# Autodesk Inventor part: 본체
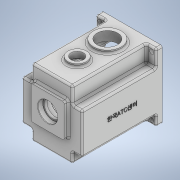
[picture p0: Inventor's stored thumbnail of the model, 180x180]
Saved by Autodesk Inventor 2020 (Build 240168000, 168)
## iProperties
Created: 2022-01
Part Number: 본체
Material: 일반
Document SubType Name: Modeling
Designer: user
Density: 1 g/cm^3
Appearance: 기본값
Author: user
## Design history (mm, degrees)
sketch "스케치1"
  geometry: L1 (-49, 55)-(49, 55); L2 (49, 55)-(49, -55); L3 (49, -55)-(-49, -55); L4 (-49, -55)-(-49, 55); L5 (-49, 55)-(49, -55); L6 (49, 55)-(-49, -55); 1 further point
  constraints: 12 end point, 2 midpoint, 2 parallel, 1 horizontal, 1 perpendicular
  dimensions: "d0" = 98 distance of L2.end L3.end; "d1" = 110 distance of L1.end L2.end
extrude "돌출1" new body sketch "스케치1" distance "d2" = 10; taper "d3" = 0 deg
sketch "스케치2"
  geometry: L1 (49, 55)-(-49, 55) reference; L2 (-49, 55)-(-33, 55); L3 (-33, 55)-(-33, 28); L4 (-33, 28)-(-49, 28); L5 (-49, 28)-(-49, 55); L6 (49, -55)-(49, 55) reference; L7 (49, 55)-(33, 55); L8 (33, 55)-(33, 28); L9 (33, 28)-(49, 28); L10 (49, 28)-(49, 55); L11 (-49, -55)-(49, -55) reference; L12 (-49, -55)-(-33, -55); L13 (-33, -55)-(-33, -38); L14 (-33, -38)-(-49, -38); L15 (-49, -38)-(-49, -55); L16 (49, -55)-(33, -55); L17 (33, -55)-(33, -38); L18 (33, -38)-(49, -38); L19 (49, -38)-(49, -55); L20 (-49, 28)-(-49, -38); L21 (-49, 55)-(-49, -55) reference; 6 further points
  constraints: 34 end point, 8 parallel, 4 horizontal, 4 perpendicular, 2 point on line, 1 collinear
  dimensions: "d10" = 16 distance between parallel lines of L5 L3; "d11" = 16 distance between parallel lines of L10 L8; "d12" = 16 distance between parallel lines of L15 L13; "d13" = 27 distance of L9.end L1.start; "d14" = 27 distance of L4.end L1.end; "d15" = 17 distance of L14.end L11.start
extrude "돌출2" join sketch "스케치2" distance "d16" = 120; taper "d17" = 0 deg
sketch "스케치3"
  geometry: L1 (-27, 33)-(27, 33); L2 (27, 33)-(27, -21); L3 (27, -21)-(-27, -21); L4 (-27, -21)-(-27, 33); L5 (-27, 33)-(27, -21); L6 (27, 33)-(-27, -21); L7 (-33, -55)-(33, -55) reference; 2 further points
  constraints: 12 end point, 2 midpoint, 2 parallel, 1 horizontal, 1 perpendicular
  dimensions: "d18" = 61 distance from line of L7 point (0, 6); "d19" = 54 distance of L1.start L1.end; "d20" = 54 distance of L3.end L1.start; "d21" = 27 distance from line of point (0, 0) L4
extrude "돌출3" join sketch "스케치3" distance "d22" = 7; taper "d23" = 0 deg
sketch "스케치5"
  geometry: L1 (49, -55)-(-49, -55) reference; L2 (49, 55)-(49, -55) reference; L3 (0, -5)-(0, 45); L4 (0, 45)-(-23, 45); L5 (-23, 45)-(-23, -5); L6 (-23, -5)-(0, -5); L7 (-23, 45)-(23, 45); L8 (23, 45)-(23, -5); L9 (23, -5)-(-23, -5); L10 (-23, -5)-(-23, 45); C1 r 42 at (0, -5); 3 further points
  constraints: 16 end point, 4 perpendicular, 2 parallel, 1 centre point, 1 horizontal, 1 vertical
  dimensions: "d25" = 84 diameter of C1; "d26" = 50 distance from line of L1 L3.start; "d27" = 49 distance from line of L3.start L2; "d28" = 50 distance of L3.start L3.end; "d29" = 23 distance of L3.end L4.end; "d30" = 46 distance of L8.end L9.end; "d31" = 50 distance of L7.end L8.end
extrude "돌출4" cut sketch "스케치5" distance "d32" = 121; taper "d33" = 0 deg
sketch "스케치7"
  geometry: L1 (23, 45)-(23, 30.143) reference; L2 (-23, 45)-(23, 45) reference; L3 (-23, 30.143)-(-23, 45) reference; L4 (26, 31.729)-(26, 48); L5 (26, 48)-(-26, 48); L6 (-26, 48)-(-26, 31.729); A1 r 42 centre (0, -5) between (-23, 30.143) and (23, 30.143) reference; A2 r 45 centre (0, -5) between (-26, 31.729) and (26, 31.729); 1 further point
  constraints: 6 end point, 2 point on circle, 1 centre point, 3 other
  dimensions: "d38" = 3 radial gap between concentric circles of A1 A2
extrude "돌출5" cut sketch "스케치7" distance "d39" = 9; taper "d40" = 0 deg
sketch "스케치8" dims "d41" = 72
  geometry: L1 (36, -9)-(45.904, -9); L2 (45.904, -9)-(45.508, -1); L3 (45.508, -1)-(36, -1); A1 r 42 centre (0, -5) between (-23, 30.143) and (23, 30.143) reference; A2 r 4 centre (36, -5) between (36, -1) and (36, -9); 2 further points
  constraints: 6 end point, 2 horizontal alignment, 2 point on circle, 2 tangent, 1 centre point, 1 coincident, 1 horizontal, 1 parallel, 2 other
  dimensions: "d42" = 8 diameter of A2
extrude "돌출6" join sketch "스케치8" stored distance "d43" = 9; taper "d44" = 0 deg
sketch "스케치9"
  geometry: 1 further point
sketch "스케치10"
  geometry: L1 (-36, -9)-(-41.809, -9) reference; L2 (41.809, -9)-(36, -9) reference; L3 (36, -1)-(41.809, -1) reference; L4 (23, 45)-(23, 30.143) reference; L5 (-23, 45)-(23, 45) reference; L6 (-23, 30.143)-(-23, 45) reference; L7 (-41.809, -1)-(-36, -1) reference; L8 (0, -5)-(0, -25); L9 (0, -5)-(0, 6); C1 r 15 at (0, -25); C2 r 21 at (0, 6); A1 r 42 centre (0, -5) between (-41.809, -9) and (41.809, -9) reference; A2 r 4 centre (36, -5) between (36, -1) and (36, -9) reference; A3 r 42 centre (0, -5) between (41.809, -1) and (23, 30.143) reference; A4 r 42 centre (0, -5) between (-23, 30.143) and (-41.809, -1) reference; A5 r 4 centre (-36, -5) between (-36, -9) and (-36, -1) reference; 3 further points
  constraints: 4 end point, 2 centre point, 2 coincident, 2 vertical
  dimensions: "d45" = 20 distance of L8.start L8.end; "d46" = 30 diameter of C1; "d47" = 11 distance of L8.start L9.end; "d48" = 42 diameter of C2
extrude "돌출7" join sketch "스케치10" distance "d49" = 7; taper "d50" = 0 deg
sketch "스케치11"
  geometry: L1 (49, -89)-(49, 0); L2 (98, 0)-(0, 0) reference; C1 r 22.5 at (49, -40); C2 r 15 at (49, -89); 1 further point
  constraints: 2 centre point, 2 end point, 1 midpoint, 1 point on line, 1 vertical
  dimensions: "d51" = 45 diameter of C1; "d52" = 30 diameter of C2; "d53" = 40 distance of C1.centre L1.end; "d54" = 49 distance of L1.start C1.centre
extrude "돌출8" join sketch "스케치11" distance "d55" = 5; taper "d56" = 0 deg
sketch "스케치12"
  geometry: C1 r 15 at (0, 0) reference; C2 r 10 at (0, 0); 1 further point
  constraints: 1 centre point, 1 coincident
  dimensions: "d57" = 20 diameter of C2
extrude "돌출9" cut sketch "스케치12" distance "d58" = 26.25; taper "d59" = 0 deg
sketch "스케치13"
  geometry: C1 r 22.5 at (0, 0) reference; 2 further points
  constraints: 1 coincident
hole "구멍1" sketch "스케치13" at (0, 0) diameter "d60" = 33.376; stored, may be unused: countersink angle "d64" = 90 deg, drill point angle "d66" = 0 deg; dims "d61" = 70, "d62" = 4, "d63" = 2, "d65" = 77.3
sketch "스케치14"
  geometry: C1 r 10 at (23, -32) reference; C2 r 15 at (23, -32); 1 further point
  constraints: 1 centre point, 1 coincident
  dimensions: "d67" = 30 diameter of C2
extrude "돌출10" cut sketch "스케치14" distance "d68" = 5; taper "d69" = 0 deg
chamfer "모따기1" distance "d70" = 1; stored, may be unused: second distance "d71" = 2, angle "d72" = 45 deg
sketch "스케치15"
  geometry: L1 (27, 33)-(-27, 33) reference; L2 (0, 33)-(0, 6); C1 r 14 at (0, 6); 1 further point
  constraints: 2 end point, 1 centre point, 1 coincident, 1 midpoint, 1 vertical
  dimensions: "d73" = 27 distance of L2.start L2.end; "d74" = 28 diameter of C1
extrude "돌출11" cut sketch "스케치15" distance "d75" = 88.75; taper "d76" = 0 deg
sketch "스케치16"
  geometry: C1 r 14 at (0, 6) reference; C2 r 16 at (0, 6); 1 further point
  constraints: 1 centre point, 1 coincident
  dimensions: "d77" = 32 diameter of C2
extrude "돌출12" cut sketch "스케치16" distance "d78" = 8.3; taper "d79" = 0 deg
fillet "모깎기1" dims "d80" = 0.3
chamfer "모따기2" distance "d81" = 0.8; stored, may be unused: second distance "d82" = 2, angle "d83" = 30 deg
sketch "스케치18"
  geometry: C1 r 17.5 at (0, 6); A1 r 21 centre (0, 6) between (8.978, -12.984) and (-8.978, -12.984) reference; 1 further point
  constraints: 1 centre point, 1 coincident
  dimensions: "d84" = 35 diameter of C1
extrude "돌출13" cut sketch "스케치18" distance "d85" = 10; taper "d86" = 0 deg
fillet "모깎기2" dims "d87" = 0.3
sketch "스케치20"
  geometry: C1 r 9.5 at (0, -25); A1 r 15 centre (0, -25) between (-8.978, -12.984) and (8.978, -12.984) reference; 1 further point
  constraints: 1 centre point, 1 coincident
  dimensions: "d88" = 19 diameter of C1
extrude "돌출14" cut sketch "스케치20" distance "d89" = 10; taper "d90" = 0 deg
sketch "스케치21"
  geometry: C1 r 9.5 at (0, -25) reference; C2 r 11 at (0, -25); 1 further point
  constraints: 1 centre point, 1 coincident
  dimensions: "d91" = 22 diameter of C2
extrude "돌출15" cut sketch "스케치21" distance "d92" = 7; taper "d93" = 0 deg
fillet "모깎기3" dims "d94" = 3
fillet "모깎기4" dims "d95" = 0.3
chamfer "모따기3" distance "d96" = 1; stored, may be unused: second distance "d97" = 2, angle "d98" = 30 deg
chamfer "모따기4" distance "d99" = 1; stored, may be unused: second distance "d100" = 2, angle "d101" = 30 deg
fillet "모깎기5" dims "d102" = 3
fillet "모깎기6" dims "d103" = 3
fillet "모깎기7" dims "d104" = 3
fillet "모깎기8" dims "d105" = 6
fillet "모깎기9" dims "d106" = 3
fillet "모깎기10" dims "d107" = 3
fillet "모깎기11" dims "d108" = 3
fillet "모깎기12" dims "d109" = 3
chamfer "모따기5" distance "d110" = 1; stored, may be unused: second distance "d111" = 2, angle "d112" = 30 deg
sketch "스케치23"
  geometry: C1 r 36 at (0, -5); A1 r 46 centre (0, -5) between (-27.792, 31.655) and (27.792, 31.655) reference; A2 r 4 centre (-36, -5) between (-36, -9) and (-36, -1) reference; 2 further points
  constraints: 2 coincident, 1 centre point
  dimensions: "d113" = 72 diameter of C1
hole "구멍2" sketch "스케치23" at (-36, -5) diameter "d114" = 3.242; stored, may be unused: countersink angle "d118" = 90 deg, drill point angle "d120" = 118 deg; dims "d115" = 7, "d116" = 4, "d117" = 2, "d119" = 9
sketch "스케치24"
  geometry: L1 (-49, 55)-(49, 55) reference; L2 (-49, -55)-(-49, 55) reference; C1 r 3.5 at (-42, 48); 1 further point
  constraints: 1 centre point
  dimensions: "d121" = 7 diameter of C1; "d122" = 7 distance from line of L1 C1.centre; "d123" = 7 distance from line of C1.centre L2
extrude "돌출16" cut sketch "스케치24" distance "d124" = 30.5; taper "d125" = 0 deg
fillet "모깎기13" dims "d132" = 3
fillet "모깎기14" dims "d133" = 3
fillet "모깎기15" dims "d134" = 3
fillet "모깎기16" dims "d135" = 3
fillet "모깎기17" dims "d136" = 3
fillet "모깎기18" dims "d137" = 3
fillet "모깎기19" dims "d138" = 3
fillet "모깎기20" dims "d139" = 3
sketch "스케치25"
  geometry: L1 (-130, 104)-(-130, 83) reference; L2 (-13, 80)-(-127, 80) reference; 2 further points
  constraints: 1 other
  dimensions: "d140" = 65 distance from line of point (-65, 47) L1; "d141" = 33 distance from line of point (-65, 47) L2
feature "엠보싱1" sketch "스케치25" dims "d142" = 0.5, "d143" = 0
node "솔리드1"
mirror "미러1"
mirror "미러2"
pattern_linear "직사각형 패턴1" dims "d128" = 84, "d131" = 96
node "투영된 루프2"
node "투영된 루프3"
feature "A9D066F2-1C7D-4E18-AEED-F7BC21143FA4" dims "d114" = 3.242, "d115" = 7, "d116" = 4, "d117" = 2, "d118" = 90 deg, "d119" = 9, "d120" = 118 deg
